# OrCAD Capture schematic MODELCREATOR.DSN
size A
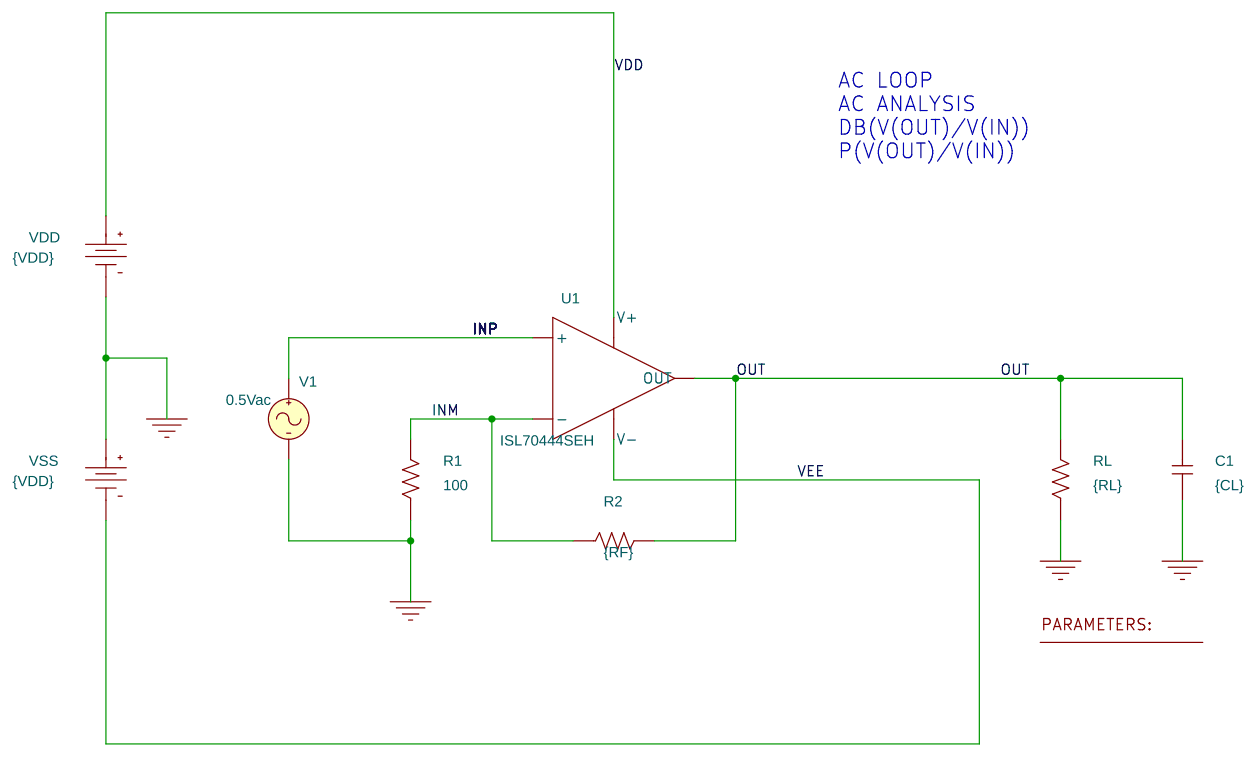
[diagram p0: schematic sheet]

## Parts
1  PARAM
C1  {CL}  [RAD/CK05]
R1  100  [AX/RC05]
R2  {RF}  [AX/RC05]
RL  {RL}  [AX/RC05]
U1  ISL70444SEH  [DIP.100/14/W.300/L.800]
V1  VAC
VDD  VDC
VSS  VDC

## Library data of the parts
1 = PARAM: CL: 10p; RF: 900; RL: 10k; VDD: 18.0
C1 = C
R1 R2 RL = R
U1 = ISL70444SEH
V1 = VAC: ACMAG: 0.5Vac
VDD VSS = VDC: DC: {VDD}

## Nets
VDD: U1.V+ VDD.0(+)
VEE: U1.V- VSS.1(-)
0: C1.1 R1.1 RL.1 V1.2(-) VDD.1(-) VSS.0(+)
INM: R1.2 R2.1 U1.-
INP: U1.+ V1.1(+)
OUT: C1.2 R2.2 RL.2 U1.OUT

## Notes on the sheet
- AC LOOP
  AC ANALYSIS
  DB(V(OUT)/V(IN))
  P(V(OUT)/V(IN))
